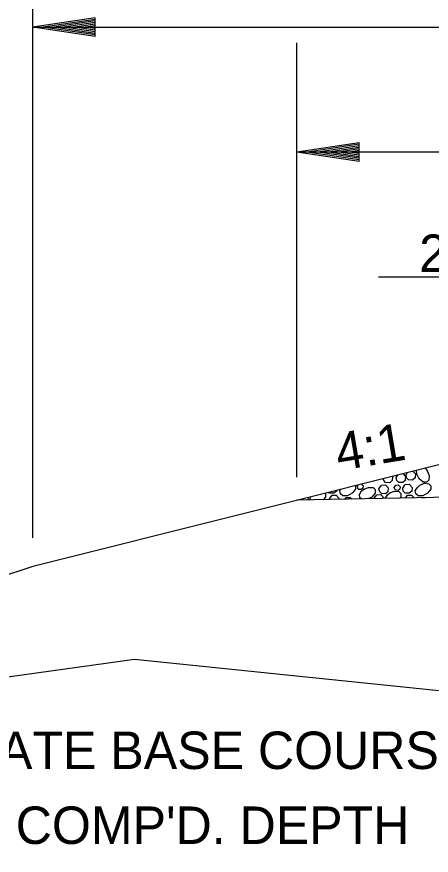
# Model space of a CAD drawing. Extents: x 2478 to 3210, y 439 to 841.
# Drawn here: x 2577.03 to 2590.31, y 576.76 to 603.61 of the extents above; entities that cross this region are included whole.
import ezdxf

# ---------------------------------------------------------------- set-up
doc = ezdxf.new("R2010")
doc.units = 0
for name, color, linetype in [('R_Annotation', 7, 'Continuous'), ('R_Dimension', 7, 'Continuous'), ('R_Exist Surface', 7, 'Continuous')]:
    doc.layers.add(name, color=color, linetype=linetype)

msp = doc.modelspace()

# ---------------------------------------------------------------- linework, layer by layer
at = {"layer": 'R_Annotation'}
for p, q in [((2597.543, 591.014), (2577.543, 586.014)), ((2605.543, 588.52), (2586.003, 588.129)), ((2577.543, 586.014), (2559.067, 579.856))]:
    msp.add_line(p, q, dxfattribs=at)
at = {"layer": 'R_Dimension'}
for p, q in [((2577.543, 586.924), (2577.543, 604.281)), ((2579.543, 603.581), (2577.543, 603.281)), ((2579.543, 603.531), (2577.877, 603.281)), ((2579.543, 603.48), (2578.221, 603.281)), ((2579.543, 603.43), (2578.554, 603.281)), ((2579.543, 603.379), (2578.893, 603.281)), ((2579.543, 603.328), (2579.227, 603.281)), ((2579.543, 602.981), (2579.543, 603.581)), ((2577.543, 603.281), (2605.543, 603.281)), ((2579.543, 602.981), (2577.543, 603.281)), ((2579.543, 603.031), (2577.877, 603.281)), ((2579.543, 603.082), (2578.221, 603.281)), ((2579.543, 603.132), (2578.554, 603.281)), ((2579.543, 603.184), (2578.893, 603.281)), ((2579.543, 603.234), (2579.227, 603.281)), ((2586.003, 588.866), (2586.003, 602.781)), ((2588.003, 599.581), (2586.003, 599.281)), ((2588.003, 598.981), (2588.003, 599.581)), ((2588.003, 599.531), (2586.337, 599.281)), ((2588.003, 599.48), (2586.681, 599.281)), ((2588.003, 599.43), (2587.014, 599.281)), ((2588.003, 599.379), (2587.353, 599.281)), ((2588.003, 599.328), (2587.687, 599.281)), ((2666.995, 599.281), (2586.003, 599.281)), ((2588.003, 598.981), (2586.003, 599.281)), ((2588.003, 599.031), (2586.337, 599.281)), ((2588.003, 599.082), (2586.681, 599.281)), ((2588.003, 599.132), (2587.014, 599.281)), ((2588.003, 599.184), (2587.353, 599.281)), ((2588.003, 599.234), (2587.687, 599.281)), ((2588.615, 595.281), (2601.539, 595.281)), ((2589.183, 588.864), (2589.24, 588.939)), ((2589.503, 588.944), (2589.549, 589.016)), ((2587.943, 588.579), (2587.976, 588.623)), ((2586.075, 588.131), (2586.072, 588.147)), ((2586.367, 588.221), (2586.357, 588.137)), ((2587.057, 588.151), (2587.053, 588.174)), ((2588.481, 588.179), (2588.478, 588.194))]:
    msp.add_line(p, q, dxfattribs=at)
for points in [[(2590.105, 589.155), (2590.123, 589.144), (2590.188, 589.064)], [(2589.056, 588.893), (2589.063, 588.884), (2589.053, 588.759), (2588.978, 588.689), (2588.848, 588.694), (2588.788, 588.759), (2588.77, 588.821)], [(2589.406, 588.98), (2589.488, 588.889), (2589.468, 588.759), (2589.393, 588.694), (2589.268, 588.704), (2589.208, 588.764), (2589.183, 588.864)], [(2589.723, 589.059), (2589.808, 588.974), (2589.788, 588.844), (2589.708, 588.779), (2589.578, 588.784), (2589.518, 588.844), (2589.503, 588.944)], [(2590.178, 589.069), (2590.238, 588.924), (2590.228, 588.779), (2590.168, 588.714), (2590.053, 588.714), (2589.923, 588.819), (2589.843, 588.964), (2589.839, 589.088)], [(2587.878, 588.598), (2587.883, 588.594), (2587.883, 588.484), (2587.778, 588.354), (2587.628, 588.274), (2587.473, 588.274), (2587.398, 588.334), (2587.383, 588.444), (2587.409, 588.481)], [(2588.071, 588.646), (2588.123, 588.594), (2588.113, 588.519), (2588.068, 588.474), (2587.993, 588.479), (2587.953, 588.519), (2587.943, 588.579)], [(2588.481, 588.749), (2588.473, 588.744), (2588.461, 588.744)], [(2588.628, 588.494), (2588.718, 588.619), (2588.843, 588.624), (2588.933, 588.529), (2588.918, 588.404), (2588.843, 588.334), (2588.713, 588.344), (2588.658, 588.404), (2588.628, 588.494)], [(2589.123, 588.544), (2589.173, 588.619), (2589.248, 588.624), (2589.308, 588.564), (2589.298, 588.484), (2589.248, 588.444), (2589.173, 588.459), (2589.138, 588.484), (2589.123, 588.544)], [(2589.393, 588.519), (2589.468, 588.639), (2589.603, 588.644), (2589.698, 588.544), (2589.683, 588.419), (2589.598, 588.354), (2589.468, 588.359), (2589.408, 588.419), (2589.393, 588.519)], [(2589.938, 588.614), (2590.088, 588.674), (2590.228, 588.659), (2590.298, 588.594), (2590.298, 588.484), (2590.193, 588.354), (2590.043, 588.274), (2589.888, 588.274), (2589.813, 588.334), (2589.798, 588.444), (2589.873, 588.549), (2589.943, 588.614)], [(2586.915, 588.357), (2586.923, 588.349), (2586.918, 588.234), (2586.846, 588.146)], [(2587.271, 588.446), (2587.268, 588.419), (2587.183, 588.354), (2587.053, 588.359), (2587.027, 588.385)], [(2587.053, 588.174), (2587.133, 588.289), (2587.263, 588.294), (2587.353, 588.199), (2587.349, 588.156)], [(2588.072, 588.171), (2588.018, 588.204), (2588.013, 588.319), (2588.078, 588.429), (2588.158, 588.489)], [(2588.148, 588.484), (2588.303, 588.544), (2588.443, 588.534), (2588.508, 588.474), (2588.508, 588.359), (2588.403, 588.234), (2588.288, 588.175)], [(2588.478, 588.194), (2588.563, 588.309), (2588.688, 588.314), (2588.783, 588.224), (2588.778, 588.185)], [(2588.843, 588.186), (2588.843, 588.199), (2588.908, 588.304), (2588.983, 588.364)], [(2588.978, 588.364), (2589.128, 588.424), (2589.273, 588.414), (2589.338, 588.349), (2589.333, 588.234), (2589.301, 588.195)], [(2589.485, 588.199), (2589.548, 588.289), (2589.678, 588.294), (2589.763, 588.205)], [(2586.43, 588.138), (2586.428, 588.199), (2586.454, 588.242)], [(2587.538, 588.16), (2587.583, 588.219), (2587.708, 588.224), (2587.764, 588.165)], [(2589.99, 588.209), (2589.998, 588.219), (2590.123, 588.224), (2590.134, 588.212)]]:
    msp.add_lwpolyline(points, dxfattribs=at)
at = {"layer": 'R_Exist Surface'}
msp.add_lwpolyline([(2559.048, 580.013), (2580.798, 583.038), (2610.269, 580.01), (2642.749, 581.692), (2680.214, 577.819), (2705.082, 582.167)], dxfattribs=at)

# ---------------------------------------------------------------- texts
at = {"layer": 'R_Annotation'}
for s, p in [("2' (PAVED)", (2589.921, 595.442)), ('AGGREGATE BASE COURSE', (2569.419, 579.524)), ("(CLASS 7) - VAR. COMP'D. DEPTH", (2563.712, 577.124))]:
    msp.add_text(s, height=1.2, dxfattribs=at).set_placement(p)
msp.add_text('4:1', height=1.2, rotation=9.5754, dxfattribs=at).set_placement((2587.346, 589.068))

doc.saveas('drawing.dxf')
